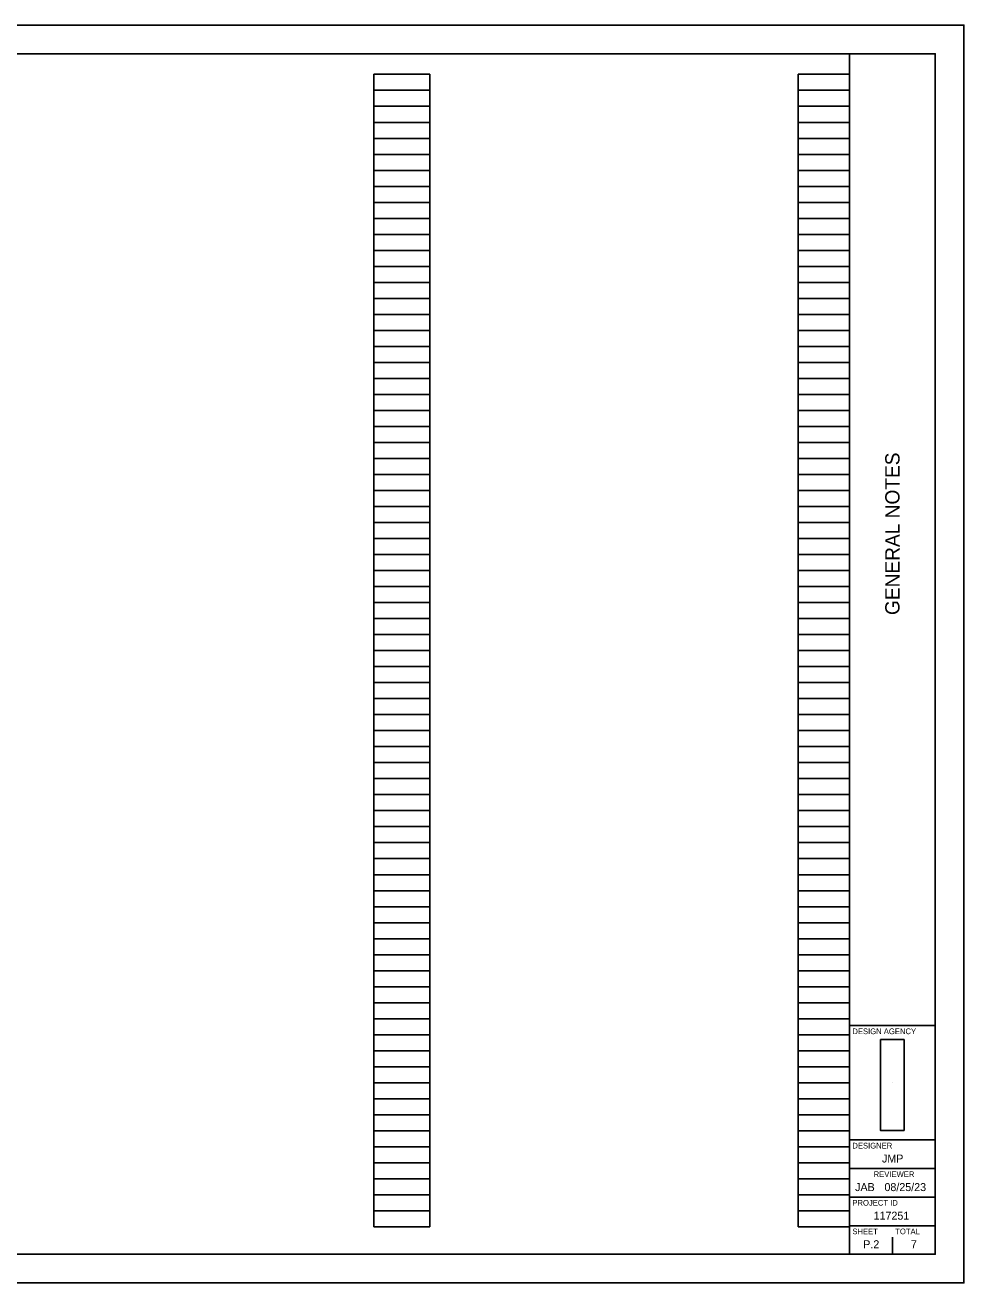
# Model space of a CAD drawing. Extents: x 0 to 34, y 0 to 22.
# Drawn here: x 17.58 to 34, y 0 to 22 of the extents above; entities that cross this region are included whole.
import ezdxf

# ---------------------------------------------------------------- set-up
doc = ezdxf.new("R2010")
doc.units = 0
for name, color, linetype in [('SH_Border', 7, 'Continuous'), ('SH_Cut_Line', 7, 'Continuous'), ('SH_Data', 7, 'Continuous'), ('SH_Text', 7, 'Continuous')]:
    doc.layers.add(name, color=color, linetype=linetype)

msp = doc.modelspace()

# ---------------------------------------------------------------- linework, layer by layer
at = {"layer": 'SH_Border'}
for p, q in [((32, 0.5), (32, 21.5)), ((32, 4.5), (33.5, 4.5)), ((32, 2.5), (33.5, 2.5)), ((32, 2), (33.5, 2)), ((32, 1.5), (33.5, 1.5)), ((32, 1), (33.5, 1))]:
    msp.add_line(p, q, dxfattribs=at)
msp.add_lwpolyline([(1.5, 21.5), (33.5, 21.5), (33.5, 0.5), (1.5, 0.5)], close=True, dxfattribs=at)
at = {"layer": 'SH_Cut_Line'}
msp.add_lwpolyline([(0, 0), (34, 0), (34, 22), (0, 22)], close=True, dxfattribs=at)
at = {"layer": 'SH_Data'}
for p, q in [((23.68, 0.98), (23.68, 21.14)), ((23.68, 21.14), (24.66, 21.14)), ((24.66, 0.98), (24.66, 21.14)), ((31.1, 0.98), (31.1, 21.14)), ((31.1, 21.14), (32, 21.14)), ((32, 0.98), (32, 21.14)), ((23.68, 20.86), (24.66, 20.86)), ((31.1, 20.86), (32, 20.86)), ((23.68, 20.58), (24.66, 20.58)), ((31.1, 20.58), (32, 20.58)), ((23.68, 20.3), (24.66, 20.3)), ((31.1, 20.3), (32, 20.3)), ((23.68, 20.02), (24.66, 20.02)), ((31.1, 20.02), (32, 20.02)), ((23.68, 19.74), (24.66, 19.74)), ((31.1, 19.74), (32, 19.74)), ((23.68, 19.46), (24.66, 19.46)), ((31.1, 19.46), (32, 19.46)), ((23.68, 19.18), (24.66, 19.18)), ((31.1, 19.18), (32, 19.18)), ((23.68, 18.9), (24.66, 18.9)), ((31.1, 18.9), (32, 18.9)), ((23.68, 18.62), (24.66, 18.62)), ((31.1, 18.62), (32, 18.62)), ((23.68, 18.34), (24.66, 18.34)), ((31.1, 18.34), (32, 18.34)), ((23.68, 18.06), (24.66, 18.06)), ((31.1, 18.06), (32, 18.06)), ((23.68, 17.78), (24.66, 17.78)), ((31.1, 17.78), (32, 17.78)), ((23.68, 17.5), (24.66, 17.5)), ((31.1, 17.5), (32, 17.5)), ((23.68, 17.22), (24.66, 17.22)), ((31.1, 17.22), (32, 17.22)), ((23.68, 16.94), (24.66, 16.94)), ((31.1, 16.94), (32, 16.94)), ((23.68, 16.66), (24.66, 16.66)), ((31.1, 16.66), (32, 16.66)), ((23.68, 16.38), (24.66, 16.38)), ((31.1, 16.38), (32, 16.38)), ((23.68, 16.1), (24.66, 16.1)), ((31.1, 16.1), (32, 16.1)), ((23.68, 15.82), (24.66, 15.82)), ((31.1, 15.82), (32, 15.82)), ((23.68, 15.54), (24.66, 15.54)), ((31.1, 15.54), (32, 15.54)), ((23.68, 15.26), (24.66, 15.26)), ((31.1, 15.26), (32, 15.26)), ((23.68, 14.98), (24.66, 14.98)), ((31.1, 14.98), (32, 14.98)), ((23.68, 14.7), (24.66, 14.7)), ((31.1, 14.7), (32, 14.7)), ((23.68, 14.42), (24.66, 14.42)), ((31.1, 14.42), (32, 14.42)), ((23.68, 14.14), (24.66, 14.14)), ((31.1, 14.14), (32, 14.14)), ((23.68, 13.86), (24.66, 13.86)), ((31.1, 13.86), (32, 13.86)), ((23.68, 13.58), (24.66, 13.58)), ((31.1, 13.58), (32, 13.58)), ((23.68, 13.3), (24.66, 13.3)), ((31.1, 13.3), (32, 13.3)), ((23.68, 13.02), (24.66, 13.02)), ((31.1, 13.02), (32, 13.02)), ((23.68, 12.74), (24.66, 12.74)), ((31.1, 12.74), (32, 12.74)), ((23.68, 12.46), (24.66, 12.46)), ((31.1, 12.46), (32, 12.46)), ((23.68, 12.18), (24.66, 12.18)), ((31.1, 12.18), (32, 12.18)), ((23.68, 11.9), (24.66, 11.9)), ((31.1, 11.9), (32, 11.9)), ((23.68, 11.62), (24.66, 11.62)), ((31.1, 11.62), (32, 11.62)), ((23.68, 11.34), (24.66, 11.34)), ((31.1, 11.34), (32, 11.34)), ((23.68, 11.06), (24.66, 11.06)), ((31.1, 11.06), (32, 11.06)), ((23.68, 10.78), (24.66, 10.78)), ((31.1, 10.78), (32, 10.78)), ((23.68, 10.5), (24.66, 10.5)), ((31.1, 10.5), (32, 10.5)), ((23.68, 10.22), (24.66, 10.22)), ((31.1, 10.22), (32, 10.22)), ((23.68, 9.94), (24.66, 9.94)), ((31.1, 9.94), (32, 9.94)), ((23.68, 9.66), (24.66, 9.66)), ((31.1, 9.66), (32, 9.66)), ((23.68, 9.38), (24.66, 9.38)), ((31.1, 9.38), (32, 9.38)), ((23.68, 9.1), (24.66, 9.1)), ((31.1, 9.1), (32, 9.1)), ((23.68, 8.82), (24.66, 8.82)), ((31.1, 8.82), (32, 8.82)), ((23.68, 8.54), (24.66, 8.54)), ((31.1, 8.54), (32, 8.54)), ((23.68, 8.26), (24.66, 8.26)), ((31.1, 8.26), (32, 8.26)), ((23.68, 7.98), (24.66, 7.98)), ((31.1, 7.98), (32, 7.98)), ((23.68, 7.7), (24.66, 7.7)), ((31.1, 7.7), (32, 7.7)), ((23.68, 7.42), (24.66, 7.42)), ((31.1, 7.42), (32, 7.42)), ((23.68, 7.14), (24.66, 7.14)), ((31.1, 7.14), (32, 7.14)), ((23.68, 6.86), (24.66, 6.86)), ((31.1, 6.86), (32, 6.86)), ((23.68, 6.58), (24.66, 6.58)), ((31.1, 6.58), (32, 6.58)), ((23.68, 6.3), (24.66, 6.3)), ((31.1, 6.3), (32, 6.3)), ((23.68, 6.02), (24.66, 6.02)), ((31.1, 6.02), (32, 6.02)), ((23.68, 5.74), (24.66, 5.74)), ((31.1, 5.74), (32, 5.74)), ((23.68, 5.46), (24.66, 5.46)), ((31.1, 5.46), (32, 5.46)), ((23.68, 5.18), (24.66, 5.18)), ((31.1, 5.18), (32, 5.18)), ((23.68, 4.9), (24.66, 4.9)), ((31.1, 4.9), (32, 4.9)), ((23.68, 4.62), (24.66, 4.62)), ((31.1, 4.62), (32, 4.62)), ((23.68, 4.34), (24.66, 4.34)), ((31.1, 4.34), (32, 4.34)), ((23.68, 4.06), (24.66, 4.06)), ((31.1, 4.06), (32, 4.06)), ((23.68, 3.78), (24.66, 3.78)), ((31.1, 3.78), (32, 3.78)), ((23.68, 3.5), (24.66, 3.5)), ((31.1, 3.5), (32, 3.5)), ((32.75, 3.5), (32.75, 3.5)), ((23.68, 3.22), (24.66, 3.22)), ((31.1, 3.22), (32, 3.22)), ((23.68, 2.94), (24.66, 2.94)), ((31.1, 2.94), (32, 2.94)), ((23.68, 2.66), (24.66, 2.66)), ((31.1, 2.66), (32, 2.66)), ((23.68, 2.38), (24.66, 2.38)), ((31.1, 2.38), (32, 2.38)), ((23.68, 2.1), (24.66, 2.1)), ((31.1, 2.1), (32, 2.1)), ((23.68, 1.82), (24.66, 1.82)), ((31.1, 1.82), (32, 1.82)), ((23.68, 1.54), (24.66, 1.54)), ((31.1, 1.54), (32, 1.54)), ((23.68, 1.26), (24.66, 1.26)), ((31.1, 1.26), (32, 1.26)), ((23.68, 0.98), (24.66, 0.98)), ((31.1, 0.98), (32, 0.98)), ((32.375, 0.675), (32.375, 0.675)), ((32.75, 0.5), (32.75, 0.8))]:
    msp.add_line(p, q, dxfattribs=at)
at = {"layer": 'SH_Text'}
msp.add_lwpolyline([(32.956, 2.664), (32.956, 4.254), (32.544, 4.254), (32.544, 2.664)], close=True, dxfattribs=at)

# ---------------------------------------------------------------- texts
at = {"layer": 'SH_Data'}
msp.add_text('GENERAL NOTES', height=0.25, rotation=90, dxfattribs=at).set_placement((32.875, 11.682))
for s, height, p in [('DESIGN AGENCY', 0.1, (32.05, 4.35)), ('DESIGNER', 0.1, (32.05, 2.35)), ('JMP', 0.14, (32.568, 2.105)), ('REVIEWER', 0.1, (32.422, 1.85)), ('JAB', 0.14, (32.098, 1.605)), ('08/25/23', 0.14, (32.611, 1.605)), ('PROJECT ID', 0.1, (32.05, 1.35)), ('117251', 0.14, (32.421, 1.105)), ('SHEET', 0.1, (32.05, 0.85)), ('TOTAL', 0.1, (32.8, 0.85)), ('P.2', 0.14, (32.24, 0.605)), ('7', 0.14, (33.074, 0.605))]:
    msp.add_text(s, height=height, dxfattribs=at).set_placement(p)

doc.saveas('drawing.dxf')
